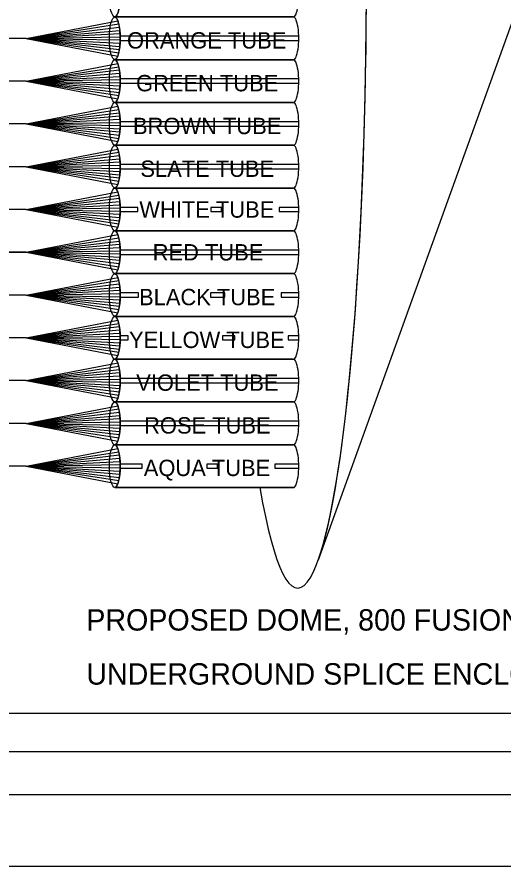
# Model space of a CAD drawing. Extents: x 1805893 to 1833564, y 708898 to 716199.
# Drawn here: x 1831784 to 1831852.1, y 714257.9 to 714377 of the extents above; entities that cross this region are included whole.
import ezdxf

# ---------------------------------------------------------------- set-up
doc = ezdxf.new("R2010")
doc.units = 0
for name, color, linetype in [('BR_P_Sub_Hidden', 7, 'Continuous'), ('SH_Border', 7, 'Continuous'), ('SH_Cut_Line', 7, 'Continuous'), ('SH_Data', 7, 'Continuous')]:
    doc.layers.add(name, color=color, linetype=linetype)

msp = doc.modelspace()

# ---------------------------------------------------------------- linework, layer by layer
at = {"layer": 'BR_P_Sub_Hidden'}
for points in [[(1831500.32, 714509.57), (1831957.51, 714509.57), (1831957.51, 714273.91), (1831500.32, 714273.91)], [(1831570.12, 714505.91), (1831894.14, 714505.91), (1831894.14, 714279.3), (1831570.12, 714279.3)]]:
    msp.add_lwpolyline(points, close=True, dxfattribs=at)
at = {"layer": 'SH_Border'}
msp.add_lwpolyline([(1831362.49, 714687.91), (1831992.49, 714687.91), (1831992.49, 714267.91), (1831362.49, 714267.91)], close=True, dxfattribs=at)
at = {"layer": 'SH_Cut_Line'}
msp.add_lwpolyline([(1831322.49, 714257.91), (1832002.49, 714257.91), (1832002.49, 714697.91), (1831322.49, 714697.91)], close=True, dxfattribs=at)
at = {"layer": 'SH_Data'}
for p, q in [((1831785.27, 714373.99), (1831798.11, 714376.46)), ((1831785.27, 714373.99), (1831798.24, 714376.01)), ((1831797.69, 714376.99), (1831822.74, 714376.99)), ((1831822.74, 714376.99), (1831797.69, 714376.99)), ((1831785.27, 714373.99), (1831798.33, 714375.56)), ((1831785.27, 714373.99), (1831798.38, 714375.11)), ((1831785.27, 714373.99), (1831727.96, 714373.99)), ((1831785.27, 714373.99), (1831727.96, 714373.99)), ((1831785.27, 714373.99), (1831798.42, 714374.66)), ((1831785.27, 714373.99), (1831798.43, 714374.21)), ((1831785.27, 714373.99), (1831798.38, 714372.86)), ((1831785.27, 714373.99), (1831798.33, 714372.41)), ((1831785.27, 714373.99), (1831798.24, 714371.96)), ((1831785.27, 714373.99), (1831798.11, 714371.51)), ((1831785.27, 714373.99), (1831798.42, 714373.31)), ((1831785.27, 714373.99), (1831798.43, 714373.76)), ((1831785.27, 714367.99), (1831798.11, 714370.46)), ((1831822.74, 714370.99), (1831797.69, 714370.99)), ((1831797.69, 714370.99), (1831822.74, 714370.99)), ((1831785.27, 714367.99), (1831798.24, 714370.01)), ((1831785.27, 714367.99), (1831798.33, 714369.56)), ((1831785.27, 714367.99), (1831798.38, 714369.11)), ((1831785.27, 714367.99), (1831727.96, 714367.99)), ((1831785.27, 714367.99), (1831727.96, 714367.99)), ((1831785.27, 714367.99), (1831798.42, 714368.66)), ((1831785.27, 714367.99), (1831798.43, 714368.21)), ((1831785.27, 714367.99), (1831798.38, 714366.86)), ((1831785.27, 714367.99), (1831798.33, 714366.41)), ((1831785.27, 714367.99), (1831798.24, 714365.96)), ((1831785.27, 714367.99), (1831798.11, 714365.51)), ((1831785.27, 714367.99), (1831798.42, 714367.31)), ((1831785.27, 714367.99), (1831798.43, 714367.76)), ((1831785.27, 714361.99), (1831798.11, 714364.46)), ((1831797.69, 714364.99), (1831822.74, 714364.99)), ((1831822.74, 714364.99), (1831797.69, 714364.99)), ((1831785.27, 714361.99), (1831798.24, 714364.01)), ((1831785.27, 714361.99), (1831798.33, 714363.56)), ((1831785.27, 714361.99), (1831798.38, 714363.11)), ((1831785.27, 714361.99), (1831727.96, 714361.99)), ((1831785.27, 714361.99), (1831727.96, 714361.99)), ((1831785.27, 714361.99), (1831798.42, 714362.66)), ((1831785.27, 714361.99), (1831798.43, 714362.21)), ((1831785.27, 714361.99), (1831798.38, 714360.86)), ((1831785.27, 714361.99), (1831798.33, 714360.41)), ((1831785.27, 714361.99), (1831798.24, 714359.96)), ((1831785.27, 714361.99), (1831798.11, 714359.51)), ((1831785.27, 714361.99), (1831798.42, 714361.31)), ((1831785.27, 714361.99), (1831798.43, 714361.76)), ((1831785.27, 714355.99), (1831798.11, 714358.46)), ((1831797.69, 714358.99), (1831822.74, 714358.99)), ((1831822.74, 714358.99), (1831797.69, 714358.99)), ((1831785.27, 714355.99), (1831798.24, 714358.01)), ((1831785.27, 714355.99), (1831798.33, 714357.56)), ((1831785.27, 714355.99), (1831798.38, 714357.11)), ((1831785.27, 714355.99), (1831727.96, 714355.99)), ((1831785.27, 714355.99), (1831727.96, 714355.99)), ((1831785.27, 714355.99), (1831798.42, 714356.66)), ((1831785.27, 714355.99), (1831798.43, 714356.21)), ((1831785.27, 714355.99), (1831798.38, 714354.86)), ((1831785.27, 714355.99), (1831798.33, 714354.41)), ((1831785.27, 714355.99), (1831798.24, 714353.96)), ((1831785.27, 714355.99), (1831798.11, 714353.51)), ((1831785.27, 714355.99), (1831798.42, 714355.31)), ((1831785.27, 714355.99), (1831798.43, 714355.76)), ((1831785.27, 714349.99), (1831798.11, 714352.46)), ((1831797.69, 714352.99), (1831822.74, 714352.99)), ((1831822.74, 714352.99), (1831797.69, 714352.99)), ((1831785.27, 714349.99), (1831798.24, 714352.01)), ((1831785.27, 714349.99), (1831798.33, 714351.56)), ((1831785.27, 714349.99), (1831798.38, 714351.11)), ((1831785.27, 714349.99), (1831727.96, 714349.96)), ((1831785.27, 714349.99), (1831727.96, 714349.99)), ((1831785.27, 714349.99), (1831798.42, 714350.66)), ((1831785.27, 714349.99), (1831798.43, 714350.21)), ((1831785.27, 714349.99), (1831798.38, 714348.86)), ((1831785.27, 714349.99), (1831798.33, 714348.41)), ((1831785.27, 714349.99), (1831798.24, 714347.96)), ((1831785.27, 714349.99), (1831798.11, 714347.51)), ((1831785.27, 714349.99), (1831798.42, 714349.31)), ((1831785.27, 714349.99), (1831798.43, 714349.76)), ((1831785.27, 714343.99), (1831798.11, 714346.46)), ((1831797.69, 714346.99), (1831822.74, 714346.99)), ((1831822.74, 714346.99), (1831797.69, 714346.99)), ((1831785.27, 714343.99), (1831798.24, 714346.01)), ((1831785.27, 714343.99), (1831798.33, 714345.56)), ((1831785.27, 714343.99), (1831798.38, 714345.11)), ((1831785.27, 714343.99), (1831727.96, 714343.99)), ((1831727.96, 714343.99), (1831785.27, 714343.99)), ((1831785.27, 714343.99), (1831798.42, 714344.66)), ((1831785.27, 714343.99), (1831798.43, 714344.21)), ((1831785.27, 714343.99), (1831798.38, 714342.86)), ((1831785.27, 714343.99), (1831798.33, 714342.41)), ((1831785.27, 714343.99), (1831798.24, 714341.96)), ((1831785.27, 714343.99), (1831798.11, 714341.51)), ((1831785.27, 714343.99), (1831798.42, 714343.31)), ((1831785.27, 714343.99), (1831798.43, 714343.76)), ((1831785.27, 714337.99), (1831798.11, 714340.46)), ((1831797.69, 714340.99), (1831822.74, 714340.99)), ((1831822.74, 714340.99), (1831797.69, 714340.99)), ((1831785.27, 714337.99), (1831798.24, 714340.01)), ((1831785.27, 714337.99), (1831798.33, 714339.56)), ((1831785.27, 714337.99), (1831798.38, 714339.11)), ((1831785.27, 714337.99), (1831727.96, 714337.99)), ((1831785.27, 714337.99), (1831727.96, 714337.99)), ((1831785.27, 714337.99), (1831798.42, 714338.66)), ((1831785.27, 714337.99), (1831798.43, 714338.21)), ((1831785.27, 714337.99), (1831798.38, 714336.86)), ((1831785.27, 714337.99), (1831798.33, 714336.41)), ((1831785.27, 714337.99), (1831798.24, 714335.96)), ((1831785.27, 714337.99), (1831798.11, 714335.51)), ((1831785.27, 714337.99), (1831798.42, 714337.31)), ((1831785.27, 714337.99), (1831798.43, 714337.76)), ((1831785.27, 714331.99), (1831798.11, 714334.46)), ((1831822.74, 714334.99), (1831797.69, 714334.99)), ((1831797.69, 714334.99), (1831822.74, 714334.99)), ((1831785.27, 714331.99), (1831798.24, 714334.01)), ((1831785.27, 714331.99), (1831798.33, 714333.56)), ((1831785.27, 714331.99), (1831727.96, 714331.99)), ((1831785.27, 714331.99), (1831727.96, 714331.99)), ((1831785.27, 714331.99), (1831798.38, 714333.11)), ((1831785.27, 714331.99), (1831798.42, 714332.66)), ((1831785.27, 714331.99), (1831798.43, 714332.21)), ((1831785.27, 714331.99), (1831798.38, 714330.86)), ((1831785.27, 714331.99), (1831798.33, 714330.41)), ((1831785.27, 714331.99), (1831798.24, 714329.96)), ((1831785.27, 714331.99), (1831798.11, 714329.51)), ((1831785.27, 714331.99), (1831798.42, 714331.31)), ((1831785.27, 714331.99), (1831798.43, 714331.76)), ((1831785.27, 714325.99), (1831798.11, 714328.46)), ((1831797.69, 714328.99), (1831822.74, 714328.99)), ((1831822.74, 714328.99), (1831797.69, 714328.99)), ((1831785.27, 714325.99), (1831798.24, 714328.01)), ((1831785.27, 714325.99), (1831798.33, 714327.56)), ((1831785.27, 714325.99), (1831798.38, 714327.11)), ((1831785.27, 714325.99), (1831798.42, 714326.66)), ((1831785.27, 714325.99), (1831798.43, 714326.21)), ((1831785.27, 714325.99), (1831727.96, 714325.99)), ((1831785.27, 714325.99), (1831727.96, 714325.99)), ((1831785.27, 714325.99), (1831798.38, 714324.86)), ((1831785.27, 714325.99), (1831798.33, 714324.41)), ((1831785.27, 714325.99), (1831798.24, 714323.96)), ((1831785.27, 714325.99), (1831798.11, 714323.51)), ((1831785.27, 714325.99), (1831798.42, 714325.31)), ((1831785.27, 714325.99), (1831798.43, 714325.76)), ((1831785.27, 714319.99), (1831798.11, 714322.46)), ((1831797.69, 714322.99), (1831822.74, 714322.99)), ((1831822.74, 714322.99), (1831797.69, 714322.99)), ((1831785.27, 714319.99), (1831798.24, 714322.01)), ((1831785.27, 714319.99), (1831798.33, 714321.56)), ((1831785.27, 714319.99), (1831798.38, 714321.11)), ((1831785.27, 714319.99), (1831798.42, 714320.66)), ((1831785.27, 714319.99), (1831798.43, 714320.21)), ((1831785.27, 714319.99), (1831727.96, 714319.99)), ((1831785.27, 714319.99), (1831727.96, 714319.99)), ((1831785.27, 714319.99), (1831798.38, 714318.86)), ((1831785.27, 714319.99), (1831798.33, 714318.41)), ((1831785.27, 714319.99), (1831798.24, 714317.96)), ((1831785.27, 714319.99), (1831798.11, 714317.51)), ((1831785.27, 714319.99), (1831798.42, 714319.31)), ((1831785.27, 714319.99), (1831798.43, 714319.76)), ((1831797.69, 714316.99), (1831822.74, 714316.99)), ((1831822.74, 714316.99), (1831797.69, 714316.99)), ((1831785.27, 714313.99), (1831798.11, 714316.46)), ((1831785.27, 714313.99), (1831798.24, 714316.01)), ((1831785.27, 714313.99), (1831798.33, 714315.56)), ((1831785.27, 714313.99), (1831798.38, 714315.11)), ((1831785.27, 714313.99), (1831798.42, 714314.66)), ((1831785.27, 714313.99), (1831798.43, 714314.21)), ((1831785.27, 714313.99), (1831727.96, 714313.96)), ((1831785.27, 714313.99), (1831727.96, 714313.99)), ((1831785.27, 714313.99), (1831798.38, 714312.86)), ((1831785.27, 714313.99), (1831798.33, 714312.41)), ((1831785.27, 714313.99), (1831798.24, 714311.96)), ((1831785.27, 714313.99), (1831798.11, 714311.51)), ((1831785.27, 714313.99), (1831798.42, 714313.31)), ((1831785.27, 714313.99), (1831798.43, 714313.76)), ((1831797.69, 714310.99), (1831822.74, 714310.99)), ((1831822.74, 714310.99), (1831797.69, 714310.99)), ((1831797.69, 714310.99), (1831818.05, 714310.99))]:
    msp.add_line(p, q, dxfattribs=at)
msp.add_lwpolyline([(1831826.21, 714465.18), (1831855.81, 714382.99), (1831826.21, 714300.79)], dxfattribs=at)
for points in [[(1831823.48, 714374.29), (1831798.44, 714374.29), (1831798.44, 714373.69), (1831823.48, 714373.69)], [(1831823.48, 714368.29), (1831798.44, 714368.29), (1831798.44, 714367.69), (1831823.48, 714367.69)], [(1831823.48, 714362.29), (1831798.44, 714362.29), (1831798.44, 714361.69), (1831823.48, 714361.69)], [(1831823.48, 714356.29), (1831798.44, 714356.29), (1831798.44, 714355.69), (1831823.48, 714355.69)], [(1831800.92, 714350.29), (1831798.43, 714350.29), (1831798.43, 714349.69), (1831800.92, 714349.69)], [(1831812.65, 714350.29), (1831811.17, 714350.29), (1831811.17, 714349.69), (1831812.65, 714349.69)], [(1831823.48, 714350.29), (1831820.76, 714350.29), (1831820.76, 714349.69), (1831823.48, 714349.69)], [(1831823.48, 714344.29), (1831798.44, 714344.29), (1831798.44, 714343.69), (1831823.48, 714343.69)], [(1831801.04, 714338.29), (1831798.43, 714338.29), (1831798.43, 714337.69), (1831801.04, 714337.69)], [(1831813.11, 714338.29), (1831811.13, 714338.29), (1831811.13, 714337.69), (1831813.11, 714337.69)], [(1831823.48, 714338.29), (1831821.01, 714338.29), (1831821.01, 714337.69), (1831823.48, 714337.69)], [(1831799.56, 714332.29), (1831798.43, 714332.29), (1831798.43, 714331.69), (1831799.56, 714331.69)], [(1831814.52, 714332.29), (1831812.8, 714332.29), (1831812.8, 714331.69), (1831814.52, 714331.69)], [(1831823.48, 714332.29), (1831822.02, 714332.29), (1831822.02, 714331.69), (1831823.48, 714331.69)], [(1831823.48, 714326.29), (1831798.44, 714326.29), (1831798.44, 714325.69), (1831823.48, 714325.69)], [(1831823.48, 714320.29), (1831798.44, 714320.29), (1831798.44, 714319.69), (1831823.48, 714319.69)], [(1831801.54, 714314.29), (1831798.43, 714314.29), (1831798.43, 714313.69), (1831801.54, 714313.69)], [(1831812.12, 714314.29), (1831810.6, 714314.29), (1831810.6, 714313.69), (1831812.12, 714313.69)], [(1831823.48, 714314.29), (1831820.12, 714314.29), (1831820.12, 714313.69), (1831823.48, 714313.69)]]:
    msp.add_lwpolyline(points, close=True, dxfattribs=at)
for centre, major_axis, ratio, start_param, end_param in [((1831823.34, 714382.99), (0, -86.09), 0.112175, 5.702888, 10.005075), ((1831823.34, 714382.99), (0, -86.09), 0.112175, 0.302036, 2.839557), ((1831797.69, 714379.99), (0, -3), 0.25, 0, 3.141593), ((1831822.74, 714379.99), (0, -3), 0.25, 0, 3.141593), ((1831822.74, 714379.99), (0, -3), 0.25, 0, 3.141593), ((1831797.69, 714373.99), (0, -3), 0.25, 0, 3.141593), ((1831822.74, 714373.99), (0, -3), 0.25, 0, 3.141593), ((1831822.74, 714373.99), (0, -3), 0.25, 0, 3.141593), ((1831797.69, 714367.99), (0, -3), 0.25, 0, 3.141593), ((1831822.74, 714367.99), (0, -3), 0.25, 0, 3.141593), ((1831822.74, 714367.99), (0, -3), 0.25, 0, 3.141593), ((1831797.69, 714361.99), (0, -3), 0.25, 0, 3.141593), ((1831822.74, 714361.99), (0, -3), 0.25, 0, 3.141593), ((1831822.74, 714361.99), (0, -3), 0.25, 0, 3.141593), ((1831797.69, 714355.99), (0, -3), 0.25, 0, 3.141593), ((1831822.74, 714355.99), (0, -3), 0.25, 0, 3.141593), ((1831822.74, 714355.99), (0, -3), 0.25, 0, 3.141593), ((1831797.69, 714349.99), (0, -3), 0.25, 0, 3.141593), ((1831822.74, 714349.99), (0, -3), 0.25, 0, 3.141593), ((1831822.74, 714349.99), (0, -3), 0.25, 0, 3.141593), ((1831797.69, 714343.99), (0, -3), 0.25, 0, 3.141593), ((1831822.74, 714343.99), (0, -3), 0.25, 0, 3.141593), ((1831822.74, 714343.99), (0, -3), 0.25, 0, 3.141593), ((1831797.69, 714337.99), (0, -3), 0.25, 0, 3.141593), ((1831822.74, 714337.99), (0, -3), 0.25, 0, 3.141593), ((1831822.74, 714337.99), (0, -3), 0.25, 0, 3.141593), ((1831797.69, 714331.99), (0, -3), 0.25, 0, 3.141593), ((1831822.74, 714331.99), (0, -3), 0.25, 0, 3.141593), ((1831822.74, 714331.99), (0, -3), 0.25, 0, 3.141593), ((1831797.69, 714325.99), (0, -3), 0.25, 0, 3.141593), ((1831822.74, 714325.99), (0, -3), 0.25, 0, 3.141593), ((1831822.74, 714325.99), (0, -3), 0.25, 0, 3.141593), ((1831797.69, 714319.99), (0, -3), 0.25, 0, 3.141593), ((1831822.74, 714319.99), (0, -3), 0.25, 0, 3.141593), ((1831822.74, 714319.99), (0, -3), 0.25, 0, 3.141593), ((1831797.69, 714313.99), (0, -3), 0.25, 0, 3.141593), ((1831822.74, 714313.99), (0, -3), 0.25, 0, 3.141593), ((1831822.74, 714313.99), (0, -3), 0.25, 0, 3.141593)]:
    msp.add_ellipse(centre, major_axis=major_axis, ratio=ratio, start_param=start_param, end_param=end_param, dxfattribs=at)
for centre in [(1831797.69, 714379.99), (1831797.69, 714373.99), (1831797.69, 714367.99), (1831797.69, 714361.99), (1831797.69, 714355.99), (1831797.69, 714349.99), (1831797.69, 714343.99), (1831797.69, 714337.99), (1831797.69, 714331.99), (1831797.69, 714325.99), (1831797.69, 714319.99), (1831797.69, 714313.99)]:
    msp.add_ellipse(centre, major_axis=(0, -3), ratio=0.25, dxfattribs=at)

# ---------------------------------------------------------------- texts
for s, height, p in [('ORANGE TUBE', 2.2947, (1831799.41, 714372.56)), ('GREEN TUBE', 2.295, (1831800.67, 714366.56)), ('BROWN TUBE', 2.295, (1831800.25, 714360.56)), ('SLATE TUBE', 2.295, (1831801.28, 714354.56)), ('WHITE TUBE', 2.295, (1831801.14, 714348.84)), ('RED TUBE', 2.295, (1831803.01, 714342.84)), ('BLACK TUBE', 2.295, (1831801.1, 714336.56)), ('YELLOW TUBE', 2.2947, (1831799.69, 714330.56)), ('VIOLET TUBE', 2.2947, (1831800.7, 714324.56)), ('ROSE TUBE', 2.295, (1831801.81, 714318.56)), ('AQUA TUBE', 2.295, (1831801.76, 714312.6)), ('PROPOSED DOME, 800 FUSION SPLICE, ', 3, (1831793.7, 714290.93)), ('UNDERGROUND SPLICE ENCLOSURE  DoTP2', 3, (1831793.7, 714283.35))]:
    msp.add_text(s, height=height, dxfattribs=at).set_placement(p)

doc.saveas('drawing.dxf')
